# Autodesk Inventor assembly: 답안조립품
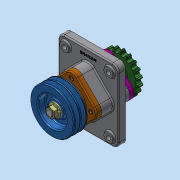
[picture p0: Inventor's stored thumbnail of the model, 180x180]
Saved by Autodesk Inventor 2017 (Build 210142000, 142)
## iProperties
Part Number: 답안조립품
Material: 일반
Document SubType Name: Assembly
Designer: MRC
Author: MRC
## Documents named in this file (16)
- C:\Users\MRC\Desktop\710707V1023\답안조립품.iam
- C:\Users\MRC\Desktop\710707V1023\본체.ipt
- C:\Users\MRC\Desktop\710707V1023\M16 너트.ipt
- C:\Users\MRC\Desktop\710707V1023\V-벨트풀리.ipt
- C:\Users\MRC\Desktop\710707V1023\멈춤나사 M4.ipt
- C:\Users\MRC\Desktop\710707V1023\베어링 6206.ipt
- C:\Users\MRC\Desktop\710707V1023\볼트 M6.ipt
- C:\Users\MRC\Desktop\710707V1023\부시.ipt
- C:\Users\MRC\Desktop\710707V1023\오일실 30x42x8.ipt
- C:\Users\MRC\Desktop\710707V1023\오일실 30x45x8.ipt
- C:\Users\MRC\Desktop\710707V1023\체인 스프로킷.ipt
- C:\Users\MRC\Desktop\710707V1023\축.ipt
- C:\Users\MRC\Desktop\710707V1023\커버A.ipt
- C:\Users\MRC\Desktop\710707V1023\커버B.ipt
- C:\Users\MRC\Desktop\710707V1023\키 6x6x18.ipt
- C:\Users\MRC\Desktop\710707V1023\키 6x6x20.ipt
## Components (3 placed, 2 different names)
1. M16 너트:1
2. V-벨트풀리:1
3. M16 너트:2
